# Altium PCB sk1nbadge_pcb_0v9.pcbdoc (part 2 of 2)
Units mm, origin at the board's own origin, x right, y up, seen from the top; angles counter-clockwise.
Board outline 99 x 74 mm, 4 copper layers (Top Layer, GND Plane, 3V Plane, Bottom Layer); 199 components, 158 nets, 800 pads, 392 vias.
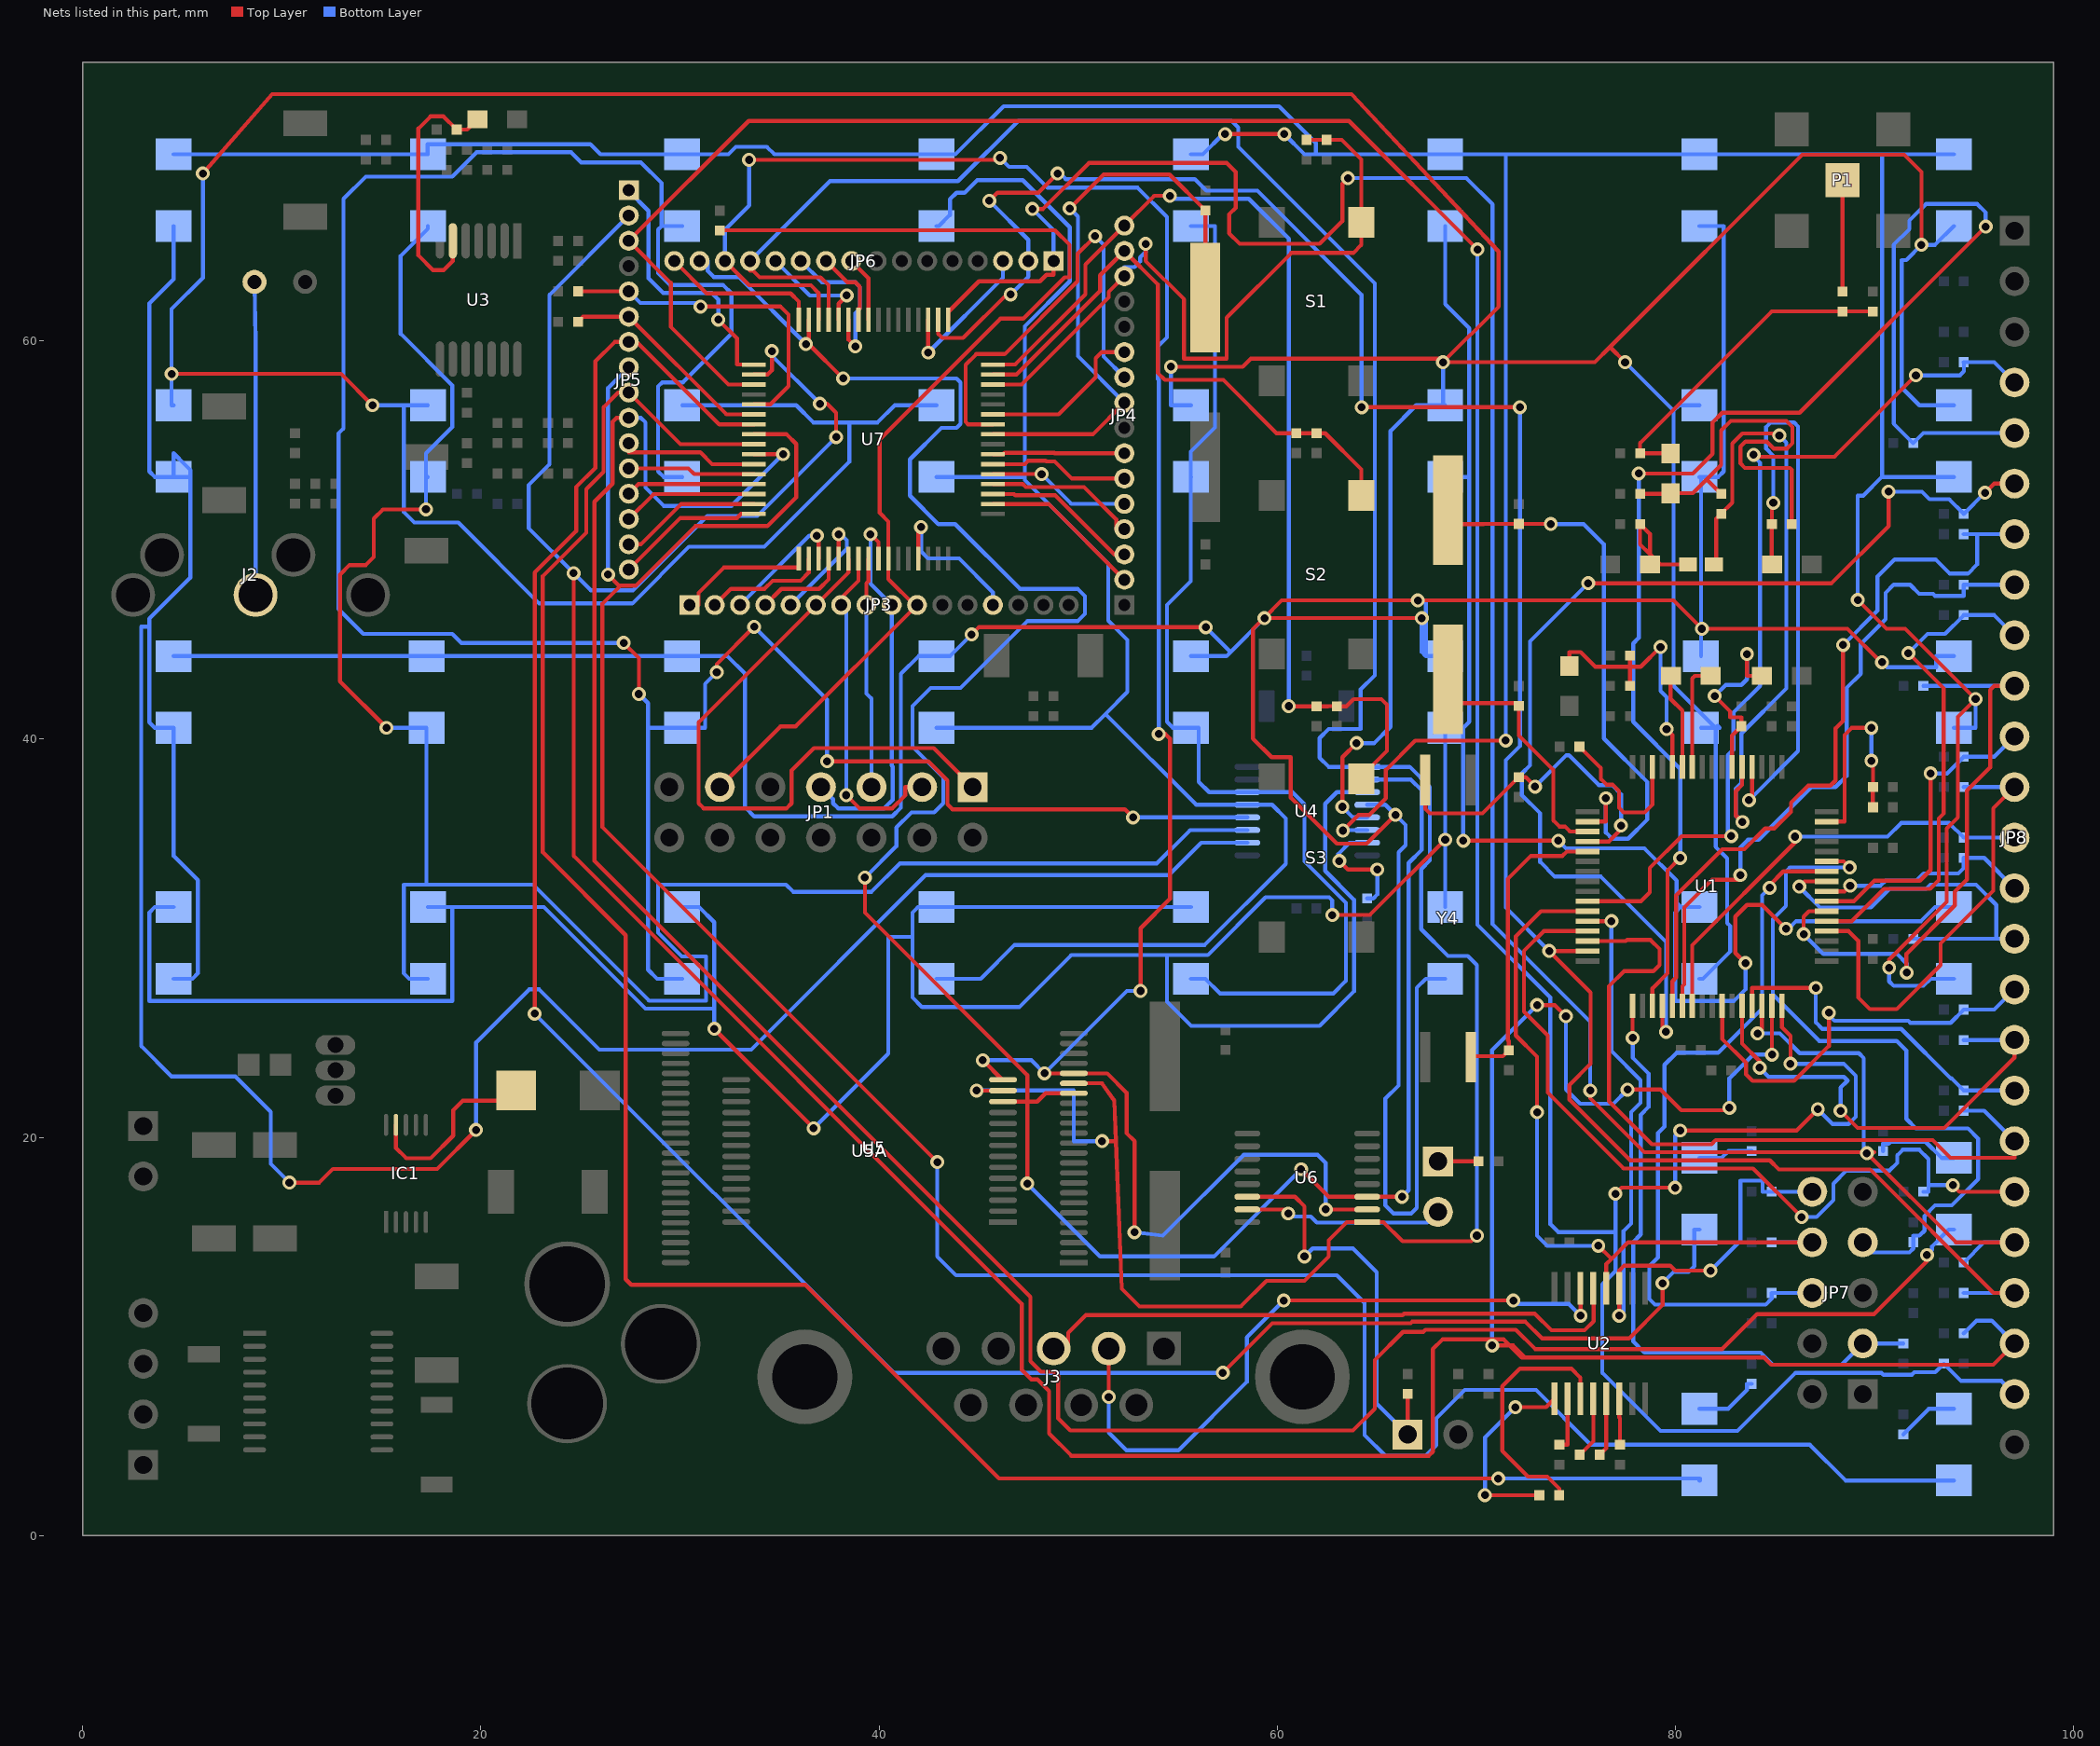
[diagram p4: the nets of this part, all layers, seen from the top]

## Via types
v1: diameter 0.7, hole 0.4, Top Layer to Bottom Layer, 392 vias

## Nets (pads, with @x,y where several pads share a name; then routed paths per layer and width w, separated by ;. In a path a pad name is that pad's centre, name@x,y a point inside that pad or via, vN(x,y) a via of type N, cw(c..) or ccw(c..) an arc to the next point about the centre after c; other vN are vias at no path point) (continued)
NetC27_2: C27.2 JP4.9 U7.9 Y2.1 | length 30.8
  Top Layer w0.2: U7.9@45.72,55.308 50.736,55.308 JP4.9@52.324,56.896 ; v1(49.581,66.65) 51.283,68.351 54.593,68.351 C27.2@56.388,66.556 Y2.1@56.388,62.162
  Bottom Layer w0.2: v1(49.581,66.65) 49.987,66.243 49.987,59.233 JP4.9@52.324,56.896
NetC29_2: C29.2 JP4.14 R27.1 S1.2@64.226,65.951 U7.14 | length 37.9
  Top Layer w0.2: U7.14@45.72,57.808 47.165,57.808 51.537,62.179 51.537,62.459 JP4.14@52.324,63.246 ; v1(53.391,64.872) 53.391,64.015 55.321,62.085 55.321,59.106 57.455,59.106 57.455,61.163 60.706,64.414 63.82,64.414 64.226,64.821 S1.2@64.226,65.951 64.226,69.113 63.243,70.096 C29.2@62.484,70.096 R27.1@61.468,70.096
  Bottom Layer w0.2: JP4.14@52.324,63.246 52.324,63.703 52.832,63.703 53.111,63.983 53.111,64.186 53.391,64.465 v1(53.391,64.872)
NetC30_2: C30.2 JP4.15 R28.1 S2.2@64.226,52.235 U7.15 | length 30
  Top Layer w0.2: U7.15@45.72,58.308 46.903,58.308 51.105,62.509 51.105,63.297 JP4.15@52.324,64.516 54,62.84 54,58.395 54.356,58.039 57.291,58.039 59.966,55.364 R28.1@60.96,55.364 C30.2@61.976,55.364 62.405,55.364 64.226,53.543 S2.2@64.226,52.235
NetC31_2: C31.2 JP4.16 R29.1 S3.2@64.226,38.011 U7.16 | length 53.1
  Top Layer w0.2: U7.16@45.72,58.808 46.838,58.808 50.368,62.339 50.368,63.83 JP4.16@52.324,65.786 53.823,67.285 v1(54.61,67.285) ; v1(60.579,41.656) 60.587,41.648 R29.1@61.976,41.648 62.552,41.648 62.56,41.656 62.984,41.656 C31.2@62.992,41.648 63.475,41.648 63.838,42.012 65.227,42.012 65.507,41.732 65.507,39.406 64.226,38.125 S3.2@64.226,38.011
  Bottom Layer w0.2: v1(54.61,67.285) 54.762,67.132 58.572,67.132 60.579,65.126 v1(60.579,41.656)
NetC32_1: C32.1 C37.2 C38.1 L2.1 | length 21.4
  Top Layer w0.2: C37.2@78.224,52.324 79.756,52.324 L2.1@79.756,52.34 79.756,52.349 80.874,52.349 81.568,53.044 ; C38.1@82.296,52.316 81.568,53.044 ; C32.1@85.844,50.8 85.844,53.526 85.75,53.619 83.49,53.619 83.261,53.848 83.261,54.686 83.515,54.94 84.582,54.94 84.938,54.585 85.598,54.585 85.877,54.864 85.877,55.677 85.573,55.982 82.779,55.982 82.296,55.499 82.296,53.772 81.568,53.044
NetC32_2: C32.2 L3.2 U1.4 | length 30.4
  Top Layer w0.2: v1(83.693,36.932) 83.844,37.083 U1.4@83.844,38.608 ; L3.2@84.852,48.768 84.836,48.768 84.836,50.513 84.844,50.521 C32.2@84.844,50.8 84.844,51.799 v1(84.912,51.867)
  Bottom Layer w0.2: v1(83.693,36.932) 86.157,39.395 86.157,55.702 85.954,55.905 84.785,55.905 84.557,55.677 84.557,54.585 84.912,54.229 v1(84.912,51.867)
NetC35_2: C35.2 R30.2 U1.63 | length 10.8
  Top Layer w0.2: U1.63@87.594,35.858 88.494,35.858 88.494,40.208 88.85,40.564 v1(89.84,40.564) ; v1(89.84,38.913) 89.924,38.829 R30.2@89.924,37.592 89.916,37.584 89.916,36.584 C35.2@89.924,36.576
  Bottom Layer w0.2: v1(89.84,38.913) v1(89.84,40.564)
NetC36_2: C36.2 L2.2 R62.1 R63.1 | length 16.5
  Top Layer w0.2: L2.2@79.756,54.34 79.756,54.356 C36.2@78.224,54.356 78.224,54.864 84.836,61.476 R63.1@89.916,61.476
NetC38_2: C38.2 L4.2 U1.5 | length 32.9
  Top Layer w0.2: L4.2@81.93,48.768 82.042,48.768 82.042,51.062 C38.2@82.296,51.316 82.855,51.875 82.855,54.846 83.356,55.347 84.861,55.347 84.963,55.245 v1(85.217,55.245) ; U1.5@83.344,38.608 83.344,37.7 83.033,37.389 83.033,36.17 v1(83.363,35.839)
  Bottom Layer w0.2: v1(83.363,35.839) 83.033,36.17 83.033,37.516 83.312,37.795 83.312,40.284 85.573,42.545 85.573,54.889 v1(85.217,55.245)
NetC39_2: C39.2 L4.1 L5.2 | length 5.9
  Top Layer w0.2: L5.2@78.724,48.768 L5.2@78.982,49.026 ; L4.1@80.63,48.768 79.24,48.768 L5.2@78.982,49.026 ; 78.724,49.284 78.724,50.3 C39.2@78.224,50.8 78.224,49.784 78.724,49.284 ; 78.724,49.284 L5.2@78.982,49.026
NetC44_2: C44.2 L6.2 U1.6 | length 9.7
  Top Layer w0.2: v1(81.966,42.164) 82.753,41.377 82.753,41.097 83.312,41.097 C44.2@83.312,40.648 82.844,40.18 U1.6@82.844,38.608 ; v1(83.591,44.272) 83.591,43.18 L6.2@84.344,43.18
  Bottom Layer w0.2: v1(81.966,42.164) 82.525,42.723 83.312,42.723 83.591,43.002 v1(83.591,44.272)
NetC45_2: C45.2 C46.2 L8.2 U1.12 | length 13.8
  Top Layer w0.2: L8.2@74.676,43.672 74.676,44.374 75.235,44.374 75.971,43.637 77.716,43.637 ; C45.2@77.716,42.672 77.716,43.637 ; C46.2@77.716,44.196 77.716,43.637 ; v1(79.248,44.628) 78.257,43.637 77.716,43.637 ; v1(79.553,40.499) 79.844,40.208 U1.12@79.844,38.608
  Bottom Layer w0.2: v1(79.248,44.628) 79.248,42.418 79.553,42.113 v1(79.553,40.499)
NetC48_1: C48.1 U1.18 Y3.1 | length 30.1
  Top Layer w0.2: Y3.1@68.58,51.494 68.58,50.8 70.35,50.8 70.358,50.808 C48.1@72.136,50.808 73.728,50.808 v1(73.736,50.8) ; U1.18@75.594,35.858 76.505,35.858 v1(76.505,37.033)
  Bottom Layer w0.2: v1(73.736,50.8) 75.387,50.8 76.403,49.784 76.403,40.03 78.588,37.846 78.588,35.966 77.622,35.001 76.81,35.001 76.505,35.306 v1(76.505,37.033)
NetC49_2: C49.2 U1.19 Y3.2 | length 13.2
  Top Layer w0.2: Y3.2@68.58,42.994 68.58,41.808 71.992,41.808 C49.2@72.136,41.664 72.136,40.183 73.863,38.456 73.863,35.916 74.168,35.611 74.449,35.611 74.701,35.358 U1.19@75.594,35.358
NetC50_2: C50.2 U1.20 Y4.1@67.435,37.945 | length 17.5
  Top Layer w0.2: Y4.1@67.435,37.945 67.435,36.502 67.666,36.271 70.307,36.271 72.128,38.092 C50.2@72.136,38.092 72.474,38.092 v1(72.949,37.617) ; U1.20@75.594,34.858 76.657,34.858 77.267,35.468 v1(77.267,35.662)
  Bottom Layer w0.2: v1(72.949,37.617) 74.524,39.192 74.651,39.192 76.149,37.694 76.81,37.694 77.267,37.236 v1(77.267,35.662)
NetC51_2: C51.2 U1.21 Y4.2@69.725,24.031 | length 15.3
  Top Layer w0.2: Y4.2@69.725,24.031 69.725,24.079 71.331,24.079 C51.2@71.628,24.376 71.628,24.841 71.577,24.892 71.577,32.969 72.746,34.138 74.32,34.138 74.541,34.358 U1.21@75.594,34.358
NetC53_1: C53.1 U2.3 | length 12.8
  Top Layer w0.2: C53.1@74.16,2.032 74.168,2.032 74.168,2.362 73.558,2.972 72.593,2.972 71.298,4.267 71.298,7.493 72.187,8.382 74.778,8.382 75.225,7.935 U2.3@75.225,6.877
NetC53_2: C53.2 U2.1 | length 9.9
  Top Layer w0.2: v1(70.434,2.032) C53.2@73.16,2.032 ; v1(71.958,6.452) 73.5,6.452 U2.1@73.925,6.877
  Bottom Layer w0.2: v1(70.434,2.032) 70.434,4.928 v1(71.958,6.452)
NetC54_2: C54.2 U2.2 | length 2.7
  Top Layer w0.2: C54.2@74.168,4.564 74.575,4.564 U2.2@74.575,6.877
NetC55_1: C55.1 U2.5 | length 3
  Top Layer w0.2: C55.1@76.192,4.064 76.525,4.397 U2.5@76.525,6.877
NetC55_2: C55.2 U2.4 | length 3.1
  Top Layer w0.2: C55.2@75.192,4.064 75.875,4.747 U2.4@75.875,6.877
NetC56_2: C56.2 U2.6 | length 2.3
  Top Layer w0.2: U2.6@77.175,6.877 77.175,5.944 77.216,5.903 C56.2@77.216,4.564
NetD1_1: D1.1 R17.2 U6.14 | length 20.7
  Top Layer w0.2: U6.14@58.496,17.018 60.884,17.018 61.366,16.535 v1(61.366,14.021) ; D1.1@66.548,5.08 R17.2@66.548,7.12
  Bottom Layer w0.2: v1(61.366,14.021) 61.773,14.427 63.805,14.427 64.999,13.233 64.999,6.629 D1.1@66.548,5.08
NetDS1_1: DS1.1 DS9.1 DS17.1 DS25.1 U4.10 | length 139.9
  Top Layer w0.2: v1(10.389,17.729) 11.887,17.729 12.573,18.415 17.805,18.415 v1(19.761,20.371)
  Bottom Layer w0.2: DS25.1@4.572,27.969 5.515,27.969 5.791,28.245 5.791,32.918 4.572,34.138 DS17.1@4.572,40.567 3.629,40.567 3.353,40.843 3.353,45.644 ; DS1.1@4.572,65.764 4.572,63.094 3.353,61.874 3.353,53.442 3.629,53.166 DS9.1@4.572,53.166 ; v1(10.389,17.729) 9.449,18.669 9.449,21.285 7.671,23.063 4.47,23.063 2.946,24.587 2.946,45.644 3.353,45.644 ; v1(19.761,20.371) 19.761,24.765 22.428,27.432 22.936,27.432 25.959,24.409 33.579,24.409 42.342,33.172 54.559,33.172 56.185,34.798 U4.10@58.496,34.798 ; 3.353,45.644 3.353,46.05 5.41,48.108 DS9.1@5.41,53.166 ; DS9.1@4.572,53.166 DS9.1@5.41,53.166 ; DS9.1@4.572,53.166 4.572,54.356 5.167,53.761 5.41,53.518 DS9.1@5.41,53.166
NetDS1_2: DS1.2 DS2.2 DS3.2 DS4.2 DS5.2 DS6.2 DS7.2 DS8.2 DS16.1 DS24.1 DS32.1 U4.6 | length 198.1
  Top Layer w0.2: v1(57.379,70.383) v1(60.35,70.383) ; v1(63.297,35.408) 64.084,36.195 64.618,36.195 65.456,37.033 65.456,38.456 66.929,39.929 v1(71.476,39.929) ; v1(89.154,46.99) 90.602,45.542 91.542,45.542 v1(95.072,42.012) 94.183,41.123 94.183,36.068 93.624,35.509 93.624,31.826 90.729,28.931 v1(90.729,28.524)
  Bottom Layer w0.2: DS1.2@4.572,69.364 DS2.2@17.323,69.364 ; DS2.2@17.345,69.364 DS2.2@17.323,69.364 ; DS5.2@55.662,69.364 56.261,69.364 57.28,70.383 v1(57.379,70.383) ; v1(60.35,70.383) 61.37,69.364 61.94,69.364 ; v1(63.297,35.408) 63.322,35.433 U4.6@64.516,35.433 ; v1(71.476,39.929) 71.476,69.367 ; v1(89.154,46.99) 89.154,52.222 89.43,52.222 90.373,53.166 ; v1(90.729,28.524) 90.729,27.838 90.957,27.61 92.453,27.61 92.812,27.969 DS32.1@93.98,27.969 ; DS24.1@93.98,40.567 95.072,40.567 v1(95.072,42.012) ; DS16.1@93.98,53.166 90.373,53.166 ; DS8.2@93.98,69.364 90.373,69.364 ; DS2.2@17.323,69.364 17.323,69.875 17.345,69.875 25.502,69.875 26.013,69.364 DS3.2@30.117,69.364 32.432,69.364 32.817,69.748 34.363,69.748 34.747,69.364 DS4.2@42.89,69.364 43.84,69.364 46.257,71.78 60.093,71.78 61.94,69.934 61.94,69.364 ; 61.94,69.364 DS6.2@68.435,69.364 68.438,69.367 71.476,69.367 ; 71.476,69.367 78,69.367 78.003,69.364 DS7.2@81.207,69.364 90.373,69.364 ; 90.373,53.166 90.373,69.364
NetDS2_1: DS2.1 DS10.1 DS18.1 DS26.1 U4.11 | length 103.8
  Top Layer w0.2: v1(15.265,40.567) 12.929,42.904 12.929,48.26 13.411,48.743 14.224,48.743 14.63,49.149 14.63,51.079 15.088,51.537 v1(17.247,51.537)
  Bottom Layer w0.2: v1(15.265,40.567) DS18.1@17.272,40.567 17.272,32.69 ; v1(17.247,51.537) DS10.1@17.247,53.166 ; DS26.1@17.345,27.969 16.405,27.969 16.129,28.245 16.129,32.69 17.272,32.69 ; DS10.1@17.345,53.166 DS10.1@17.247,53.166 ; DS2.1@17.345,65.764 17.345,65.63 15.977,64.262 15.977,60.35 18.567,57.76 18.567,55.677 17.247,54.356 DS10.1@17.247,53.166 ; U4.11@58.496,35.433 55.626,35.433 53.95,33.757 41.046,33.757 39.624,32.334 35.687,32.334 35.331,32.69 28.905,32.69 28.905,30.277 30.099,29.083 31.318,29.083 31.318,26.869 28.452,26.869 22.631,32.69 17.272,32.69
NetDS3_1: DS3.1 DS11.1 DS19.1 DS27.1 U4.12 | length 134.5
  Top Layer w0.2: v1(27.178,44.831) 27.94,44.069 v1(27.94,42.266) ; v1(31.852,43.358) 31.852,43.764 v1(33.731,45.644) ; v1(37.389,38.887) 42.469,38.887 43.434,37.922 43.434,36.728 43.688,36.474 52.349,36.474 v1(52.756,36.068)
  Bottom Layer w0.2: v1(27.178,44.831) 19.025,44.831 18.567,45.288 14.097,45.288 12.852,46.533 12.852,55.347 13.106,55.601 13.106,67.132 14.224,68.25 18.567,68.25 19.787,69.469 24.536,69.469 25.044,68.961 28.042,68.961 29.083,67.92 29.083,65.764 ; v1(27.94,42.266) 28.397,41.808 28.397,40.567 ; DS27.1@30.117,27.969 28.851,27.969 28.397,28.423 28.397,40.567 ; DS11.1@30.117,53.166 29.181,53.166 28.905,53.442 28.905,57.709 29.108,57.912 30.15,57.912 32.588,60.35 32.588,62.382 32.163,62.808 29.496,62.808 28.905,63.398 28.905,65.586 29.083,65.764 ; DS3.1@30.117,65.764 29.083,65.764 ; v1(31.852,43.358) 31.267,42.774 31.267,40.567 DS19.1@30.117,40.567 28.397,40.567 ; v1(33.731,45.644) 37.389,41.986 v1(37.389,38.887) ; v1(52.756,36.068) U4.12@58.496,36.068
NetDS4_1: DS4.1 DS12.1 DS20.1 DS28.1 U4.13 | length 83.7
  Bottom Layer w0.2: DS28.1@42.89,27.969 45.114,27.969 46.812,29.667 56.363,29.667 60.427,33.731 60.427,36.017 59.741,36.703 U4.13@58.496,36.703 55.931,36.703 51.371,41.262 ; DS20.1@42.89,40.567 50.676,40.567 51.371,41.262 ; DS12.1@42.89,53.166 47.32,53.166 ; DS4.1@42.89,65.764 43.006,65.764 43.561,66.319 43.561,67.107 43.891,67.437 44.298,67.437 44.933,68.072 47.219,68.072 49.581,65.71 49.581,62.992 47.32,60.731 47.32,53.166 ; 47.32,53.166 47.32,53.013 51.511,48.822 51.511,45.949 52.476,44.983 52.476,42.367 51.371,41.262
NetDS5_1: DS5.1 DS13.1 DS21.1 DS29.1 U4.14 | length 55.4
  Bottom Layer w0.2: DS29.1@55.662,27.969 56.388,27.969 57.128,27.229 62.814,27.229 63.449,27.864 63.449,31.775 61.366,33.858 61.366,36.728 60.757,37.338 U4.14@58.496,37.338 56.577,37.338 56.058,37.857 56.058,40.567 DS21.1@55.662,40.567 54.759,40.567 54.458,40.869 54.458,46.736 55.651,47.93 DS13.1@55.651,53.166 ; DS13.1@55.662,53.166 DS13.1@55.651,53.166 ; DS5.1@55.662,65.764 56.871,65.764 56.871,55.651 55.651,54.432 DS13.1@55.651,53.166
NetDS6_1: DS6.1 DS14.1 DS22.1 DS25.2 DS26.2 DS27.2 DS28.2 DS29.2 DS30.2 DS31.2 DS32.2 U4.3 | length 225.4
  Top Layer w0.2: v1(31.725,25.451) v1(36.716,20.46) ; v1(62.763,31.166) 64.65,31.166 v1(68.435,34.95) ; v1(69.342,34.9) v1(74.117,34.9) ; v1(83.515,28.753) 83.007,29.261 83.007,31.09 83.591,31.674 84.353,31.674 v1(85.547,30.48)
  Bottom Layer w0.2: DS25.2@4.572,31.569 3.629,31.569 3.353,31.293 3.353,26.848 18.567,26.848 18.567,31.569 ; DS26.2@17.345,31.569 18.567,31.569 ; DS27.2@30.117,31.569 30.966,31.569 31.725,30.81 31.725,26.467 ; v1(31.725,25.451) 31.725,26.467 ; v1(36.716,20.46) 40.462,24.206 40.462,30.074 41.681,30.074 ; DS29.2@55.662,31.569 DS28.2@42.89,31.569 41.957,31.569 41.681,31.293 41.681,30.074 ; v1(62.763,31.166) 62.763,31.895 62.604,32.055 59.411,32.055 56.515,29.159 54.458,29.159 ; U4.3@64.516,37.338 62.992,37.338 62.408,36.754 62.408,33.383 63.856,31.935 63.856,27.33 62.128,25.603 55.677,25.603 54.458,26.822 54.458,29.159 ; DS30.2@68.435,31.569 v1(68.435,34.95) DS22.1@68.435,40.567 69.342,40.567 ; DS14.1@68.435,53.166 69.647,53.166 ; DS6.1@68.435,65.764 68.435,61.842 69.647,60.63 69.647,53.166 ; v1(69.342,34.9) 69.342,40.567 ; v1(74.117,34.9) 74.498,34.519 78.435,34.519 80.061,32.893 80.061,31.772 80.264,31.569 ; DS31.2@81.207,31.569 80.264,31.569 ; v1(83.515,28.753) 83.515,27.432 82.931,26.848 79.985,26.848 79.985,31.293 80.261,31.569 80.264,31.569 ; v1(85.547,30.48) 85.674,30.48 86.055,30.861 92.332,30.861 93.04,31.569 DS32.2@93.98,31.569 ; 18.567,31.569 23.165,31.569 28.267,26.467 31.725,26.467 ; 41.681,30.074 41.681,27.026 42.164,26.543 47.041,26.543 49.657,29.159 54.458,29.159 ; 69.342,40.567 69.647,40.872 69.647,53.166
NetDS7_1: DS7.1 DS15.1 DS17.2 DS18.2 DS19.2 DS20.2 DS21.2 DS22.2 DS23.2 DS24.2 DS30.1 U4.4 | length 202
  Top Layer w0.2: v1(44.653,45.259) 45.012,45.618 v1(56.413,45.618) ; v1(59.36,46.076) v1(67.259,46.076) ; v1(65.938,36.195) 64.491,34.747 62.992,34.747 60.681,37.059 60.681,39.091 59.715,39.091 58.776,40.03 58.776,45.517 59.347,46.088 60.223,46.965 v1(67.056,46.965) 79.908,46.965 v1(81.331,45.542) 88.639,45.542 90.315,43.866 v1(90.373,43.866)
  Bottom Layer w0.2: DS17.2@4.572,44.167 DS18.2@17.272,44.167 DS19.2@30.117,44.167 32.388,44.167 33.274,43.282 33.274,36.576 33.731,36.119 40.665,36.119 41.097,36.551 41.097,43.282 41.983,44.167 DS20.2@42.89,44.167 43.561,44.167 v1(44.653,45.259) ; DS21.2@55.662,44.167 57.451,44.167 57.658,44.374 ; v1(56.413,45.618) 57.658,44.374 ; v1(59.36,46.076) 57.658,44.374 ; U4.4@64.516,36.703 65.43,36.703 v1(65.938,36.195) 66.446,35.687 66.446,34.671 66.091,34.315 66.091,22.606 65.43,21.946 65.43,16.586 65.837,16.18 66.726,16.18 67.005,16.459 67.005,27.512 67.462,27.969 DS30.1@68.435,27.969 ; v1(67.056,46.965) 67.462,46.965 67.462,46.076 67.462,44.167 ; v1(67.259,46.076) 67.259,44.37 67.462,44.167 ; DS22.2@68.435,44.167 67.462,44.167 ; DS15.1@81.207,53.166 DS15.1@81.28,53.166 ; DS7.1@81.207,65.764 82.423,65.764 82.423,53.442 82.147,53.166 DS15.1@81.28,53.166 ; DS23.2@81.28,44.167 v1@81.28,45.542 ; v1(81.331,45.542) v1@81.28,45.542 ; v1(90.373,43.866) 90.627,43.612 93.091,43.612 93.091,44.167 DS24.2@93.98,44.167 ; v1@81.28,45.542 DS15.1@81.28,53.166
NetDS8_1: DS8.1 DS9.2 DS10.2 DS11.2 DS12.2 DS13.2 DS14.2 DS15.2 DS16.2 DS23.1 DS31.1 U4.5 | length 277.8
  Top Layer w0.2: v1(4.47,58.344) 12.979,58.344 v1(14.558,56.766) ; v1(6.045,68.402) 9.525,72.39 63.729,72.39 71.12,64.491 71.12,61.722 v1(68.326,58.928) ; v1(54.661,58.699) 58.268,58.699 58.674,59.106 68.148,59.106 v1(68.326,58.928) ; v1(63.271,36.601) 63.271,39.091 v1(63.983,39.802) ; v1(77.47,58.928) 76.708,59.69 ; v1(92.354,64.821) 92.354,68.478 91.491,69.342 86.36,69.342 76.708,59.69 ; v1(68.326,58.928) 75.946,58.928 76.708,59.69
  Bottom Layer w0.2: DS9.2@4.572,56.766 4.47,56.766 v1(4.47,58.344) 4.47,61.595 6.045,63.17 v1(6.045,68.402) ; v1(14.558,56.766) 16.129,56.766 ; DS10.2@17.345,56.766 16.129,56.766 ; DS11.2@30.117,56.766 35.839,56.766 36.7,55.905 38.506,55.905 ; DS12.2@42.89,56.766 40.789,56.766 39.929,55.905 38.506,55.905 ; v1(54.661,58.699) 54.661,56.766 DS13.2@55.662,56.766 ; v1(63.271,36.601) 63.805,36.068 U4.5@64.516,36.068 ; v1(63.983,39.802) 64.872,39.802 65.684,40.615 65.684,55.474 66.976,56.766 DS14.2@68.326,56.766 ; v1(68.326,58.928) DS14.2@68.326,56.766 ; DS14.2@68.435,56.766 DS14.2@68.326,56.766 ; v1(77.47,58.928) 79.908,56.49 ; DS31.1@81.207,27.969 81.382,27.969 82.753,29.34 82.753,30.607 82.601,30.759 82.601,34.011 82.017,34.595 DS23.1@82.017,40.567 ; DS15.2@81.207,56.766 80.184,56.766 79.908,56.49 ; DS23.1@81.28,40.567 DS23.1@82.017,40.567 ; DS16.2@93.98,56.766 92.253,56.766 91.364,57.655 91.364,64.059 91.592,64.059 v1(92.354,64.821) 93.037,64.821 DS8.1@93.98,65.764 ; 16.129,56.766 16.129,51.41 16.662,50.876 18.872,50.876 22.936,46.812 27.61,46.812 30.455,49.657 34.239,49.657 38.506,53.924 38.506,55.905 ; 79.908,56.49 79.908,42.675 81.648,40.936 DS23.1@82.017,40.567 ; DS23.1@82.017,40.567 82.118,40.669 82.22,40.567 DS23.1@82.017,40.567
NetDS33_1: DS33.1 R16.1 | length 2
  Top Layer w0.2: DS33.1@68.072,18.796 R16.1@70.112,18.796
NetDS33_2: DS33.2 U6.15 | length 10.1
  Top Layer w0.2: U6.15@58.496,16.383 60.35,16.383 v1(60.554,16.18)
  Bottom Layer w0.2: v1(60.554,16.18) 60.706,16.027 61.682,16.027 61.986,15.723 67.539,15.723 DS33.2@68.072,16.256
NetDS34_1: DS34.1 JP5.10 U7.42 | length 127.3
  Top Layer w0.2: JP5.10@27.432,56.134 26.822,56.134 26.619,55.931 26.619,52.832 25.705,51.918 25.705,33.884 47.6,11.989 47.6,8.761 48.131,8.23 48.789,8.23 48.997,8.022 48.997,5.893 49.606,5.283 63.805,5.283 64.897,6.375 64.897,8.814 66.319,10.236 67.335,10.236 67.437,10.338 71.984,10.338 72.949,9.373 82.347,9.373 84.099,11.125 89.967,11.125 92.634,13.792 v1(92.634,14.097) ; U7.42@33.72,54.308 v1(35.179,54.308)
  Bottom Layer w0.2: JP5.10@27.432,56.134 28.042,56.134 28.27,55.905 28.27,52.629 29.185,51.714 32.585,51.714 v1(35.179,54.308) ; v1(92.634,14.097) 92.888,14.351 92.888,14.532 93.726,15.37 DS34.1@93.98,15.37
NetDS34_2: DS34.2 R20.1 | length 4.3
  Bottom Layer w0.2: R20.1@90.424,19.312 90.424,19.685 90.703,19.685 90.805,19.787 92.554,19.787 93.37,18.97 DS34.2@93.98,18.97
NetDS35_1: DS35.1 JP5.8 U7.40 | length 131.5
  Top Layer w0.2: v1(26.391,48.26) 26.949,47.701 27.003,47.701 ; U7.40@33.72,55.308 35.357,55.308 35.839,54.825 35.839,52.146 34.392,50.698 30.772,50.698 27.775,47.701 27.003,47.701 ; v1(42.926,18.764) 26.111,35.578 26.111,46.809 27.003,47.701
  Bottom Layer w0.2: v1(26.391,48.26) 26.391,57.633 JP5.8@27.432,58.674 ; v1(42.926,18.764) 42.926,14.021 43.866,13.081 62.992,13.081 64.389,11.684 64.389,5.055 65.43,4.013 67.462,4.013 67.996,4.547 67.996,5.893 69.418,7.315 73,7.315 75.743,4.572 86.744,4.572 88.544,2.772 DS35.1@93.98,2.772
NetDS35_2: DS35.2 R22.1 | length 3.1
  Bottom Layer w0.2: R22.1@91.44,5.088 92.724,6.372 DS35.2@93.98,6.372
NetDS36_1: DS36.1 JP5.9 U7.41 | length 113.9
  Top Layer w0.2: U7.41@33.72,54.808 30.028,54.808 JP5.9@27.432,57.404 26.899,57.404 26.162,56.667 26.162,53.416 25.298,52.553 25.298,50.368 23.114,48.184 23.114,34.315 27.28,30.15 27.28,12.878 27.559,12.598 36.297,12.598 46.025,2.87 v1(71.095,2.87)
  Bottom Layer w0.2: v1(71.095,2.87) 81.207,2.87 81.229,2.87 81.229,2.772 DS36.1@81.207,2.772
NetDS36_2: DS36.2 R21.1 | length 3.3
  Bottom Layer w0.2: DS36.2@81.207,6.372 82.648,6.372 83.591,7.315 83.591,7.628 R21.1@83.82,7.628
NetDS37_1: DS37.1 JP5.7 U7.39 | length 115.5
  Top Layer w0.2: v1(22.708,26.213) 22.708,48.362 24.79,50.444 24.79,52.654 25.756,53.619 25.756,58.979 26.721,59.944 JP5.7@27.432,59.944 27.838,59.944 31.974,55.808 U7.39@33.72,55.808 ; v1(57.264,8.179) 59.753,10.668 66.7,10.668 66.777,10.744 72.466,10.744 73.304,9.906 77.673,9.906 79.35,11.582 v1(79.35,12.675)
  Bottom Layer w0.2: v1(22.708,26.213) 40.742,8.179 v1(57.264,8.179) ; v1(79.35,12.675) 79.934,13.259 80.67,13.259 80.95,13.538 80.95,15.37 DS37.1@81.207,15.37
NetDS37_2: DS37.2 R23.1 | length 2.8
  Bottom Layer w0.2: DS37.2@81.207,18.97 82.321,18.97 82.663,19.312 R23.1@83.82,19.312
NetIC1_9: IC1.9 L1.1 | length 9.6
  Top Layer w0.2: IC1.9@15.74,20.628 15.74,19.464 16.256,18.948 17.475,18.948 18.618,20.091 18.618,21.361 19.101,21.844 21.268,21.844 L1.1@21.776,22.352
NetJ2_2: J2.2 MK1.2 | length 15.7
  Bottom Layer w0.2: MK1.2@8.636,62.96 8.69,59.998 J2.2@8.69,47.244
NetJ3_2: J3.2 U2.14 | length 34.4
  Top Layer w0.2: v1(51.537,6.96) 51.538,6.961 J3.2@51.538,9.396 ; v1(60.325,11.811) v1(71.857,11.811) ; U2.14@75.225,12.427 75.225,11.887 75.235,11.877 v1(75.235,11.049)
  Bottom Layer w0.2: v1(51.537,6.96) 51.537,5.182 52.426,4.293 55.042,4.293 58.471,7.722 58.471,9.957 v1(60.325,11.811) ; v1(71.857,11.811) 72.034,11.633 74.651,11.633 v1(75.235,11.049)
NetJ3_3: J3.3 U2.13 | length 30.5
  Top Layer w0.2: J3.3@48.768,9.396 49.505,9.396 49.505,10.185 50.394,11.074 66.292,11.074 66.368,11.151 72.93,11.151 73.768,10.312 75.438,10.312 75.895,10.77 75.895,11.689 75.875,11.709 U2.13@75.875,12.427
NetJP1_1: JP1.1 JP3.6 U7.54 | length 32.3
  Top Layer w0.2: U7.54@38.47,49.058 38.47,48.376 JP3.6@36.83,46.736 30.937,40.843 30.937,36.779 31.191,36.525 35.357,36.525 35.611,36.779 35.611,38.424 36.734,39.548 42.748,39.548 JP1.1@44.704,37.592
NetJP1_3: JP1.3 JP3.7 U7.55 | length 17.1
  Top Layer w0.2: JP3.7@38.1,46.736 38.1,47.085 38.97,47.955 U7.55@38.97,49.058 ; v1(38.354,37.186) 39.014,36.525 40.665,36.525 41.326,37.186 41.326,37.592 JP1.3@42.164,37.592
  Bottom Layer w0.2: JP3.7@38.1,46.736 38.354,46.482 v1(38.354,37.186)
NetJP1_5: JP1.5 JP3.8 U7.56 | length 11.6
  Top Layer w0.2: JP3.8@39.37,46.736 39.37,47.828 39.47,47.928 U7.56@39.47,49.058
  Bottom Layer w0.2: JP3.8@39.37,46.736 39.37,42.291 39.624,42.037 JP1.5@39.624,37.592
NetJP1_7: JP1.7 JP3.9 U7.57 | length 19.5
  Top Layer w0.2: v1(39.573,50.292) 39.97,49.895 U7.57@39.97,49.058
  Bottom Layer w0.2: JP1.7@37.084,37.592 37.694,36.982 37.694,36.779 37.948,36.525 40.259,36.525 40.691,36.957 40.691,38.617 40.64,38.667 JP3.9@40.64,46.736 39.573,47.803 v1(39.573,50.292)
NetJP1_11: JP1.11 JP3.10 R19.1 U7.58 | length 55.2
  Top Layer w0.2: JP1.11@32.004,37.592 35.052,40.64 35.814,40.64 JP3.10@41.841,46.667 ; R19.1@32.004,65.54 32.004,65.557 48.831,65.557 49.568,64.821 49.568,63.195 49.327,63.195 47.244,61.112 46.094,61.112 40.03,55.049 40.03,51.367 40.47,50.927 U7.58@40.47,49.058 40.47,48.037 JP3.10@41.841,46.667 ; JP3.10@41.91,46.736 JP3.10@41.841,46.667
NetJP3_1: JP3.1 U7.49 | length 7.1
  Top Layer w0.2: JP3.1@30.48,46.736 30.937,46.736 30.937,47.346 32.207,48.616 35.97,48.616 U7.49@35.97,49.058
NetJP3_2: JP3.2 U7.50 | length 6.1
  Top Layer w0.2: JP3.2@31.75,46.736 32.563,47.549 34.252,47.549 34.658,47.955 36.064,47.955 36.47,48.362 U7.50@36.47,49.058
NetJP3_3: JP3.3 U7.51 | length 6.5
  Top Layer w0.2: v1(36.881,50.216) 36.97,50.127 U7.51@36.97,49.058
  Bottom Layer w0.2: JP3.3@33.02,46.736 36.5,50.216 v1(36.881,50.216)
NetJP3_4: JP3.4 U7.52 | length 4.7
  Top Layer w0.2: JP3.4@34.29,46.736 35.097,47.543 36.989,47.543 37.47,48.024 U7.52@37.47,49.058
NetJP3_5: JP3.5 U7.53 | length 6.2
  Top Layer w0.2: U7.53@37.97,49.058 37.97,50.289 v1(37.973,50.292)
  Bottom Layer w0.2: JP3.5@35.56,46.736 38.379,49.555 38.379,49.987 38.075,50.292 v1(37.973,50.292)
NetJP3_13: JP3.13 U7.61 | length 8
  Top Layer w0.2: U7.61@41.97,49.058 41.97,50.504 v1(42.113,50.648)
  Bottom Layer w0.2: v1(42.113,50.648) 42.113,49.421 42.462,49.073 44.018,49.073 45.72,47.371 JP3.13@45.72,46.736
NetJP4_2: JP4.2 U7.2 | length 8.2
  Top Layer w0.2: U7.2@45.72,51.808 48.522,51.808 JP4.2@52.324,48.006
NetJP4_3: JP4.3 U7.3 | length 7.9
  Top Layer w0.2: U7.3@45.72,52.308 46.787,52.308 46.847,52.248 48.844,52.248 51.816,49.276 JP4.3@52.324,49.276
NetJP4_4: JP4.4 U7.4 | length 7.8
  Top Layer w0.2: U7.4@45.72,52.808 47.219,52.808 47.372,52.654 50.292,52.654 51.918,51.029 51.918,50.546 JP4.4@52.324,50.546
NetJP4_5: JP4.5 U7.5 | length 7.2
  Top Layer w0.2: U7.5@45.72,53.308 v1(48.165,53.308)
  Bottom Layer w0.2: v1(48.165,53.308) 49.657,51.816 JP4.5@52.324,51.816
NetJP4_6: JP4.6 U7.6 | length 7
  Top Layer w0.2: U7.6@45.72,53.808 47.32,53.808 47.487,53.975 48.37,53.975 48.395,53.95 48.819,53.95 49.682,53.086 JP4.6@52.324,53.086
NetJP4_7: JP4.7 U7.7 | length 6.6
  Top Layer w0.2: U7.7@45.72,54.308 46.228,54.308 46.301,54.381 48.793,54.381 48.819,54.356 JP4.7@52.324,54.356
NetJP4_10: JP4.10 U7.10 | length 22
  Top Layer w0.2: U7.10@45.72,55.808 44.471,55.808 44.348,55.931 44.348,58.801 44.882,59.334 46.31,59.334 49.968,62.992 49.968,64.37 v1(50.851,65.253)
  Bottom Layer w0.2: v1(50.851,65.253) 51.283,64.821 51.283,59.207 JP4.10@52.324,58.166
NetJP4_11: JP4.11 U7.11 | length 8.5
  Top Layer w0.2: U7.11@45.72,56.308 49.018,56.308 50.876,58.166 50.876,59.131 51.181,59.436 JP4.11@52.324,59.436
NetJP5_1: JP5.1 U7.33 | length 13.3
  Top Layer w0.2: v1(31.928,61.062) 32.868,60.122 32.868,58.808 U7.33@33.72,58.808
  Bottom Layer w0.2: JP5.1@27.432,67.564 27.432,67.513 28.423,66.523 28.423,63.144 29.159,62.408 31.598,62.408 31.928,62.078 v1(31.928,61.062)
NetJP5_5: JP5.5 R26.1 U7.37 | length 16.8
  Top Layer w0.2: R26.1@24.884,62.484 JP5.5@27.432,62.484 ; v1(31.039,61.722) 35.052,61.722 35.458,61.316 35.458,57.722 34.544,56.808 U7.37@33.72,56.808
  Bottom Layer w0.2: JP5.5@27.432,62.484 28.016,61.9 30.861,61.9 v1(31.039,61.722)
NetJP5_6: JP5.6 R24.1 U7.38 | length 11
  Top Layer w0.2: R24.1@24.884,60.96 25.138,61.214 JP5.6@27.432,61.214 32.338,56.308 U7.38@33.72,56.308
NetJP5_11: JP5.11 U7.43 | length 7
  Top Layer w0.2: JP5.11@27.432,54.864 27.432,54.407 31.024,54.407 31.623,53.808 U7.43@33.72,53.808
NetJP5_12: JP5.12 U7.44 | length 6.4
  Top Layer w0.2: JP5.12@27.432,53.594 30.429,53.594 30.715,53.308 U7.44@33.72,53.308
NetJP5_13: JP5.13 U7.45 | length 6.5
  Top Layer w0.2: JP5.13@27.432,52.324 27.916,52.808 U7.45@33.72,52.808
NetJP5_14: JP5.14 U7.46 | length 6.8
  Top Layer w0.2: JP5.14@27.432,51.054 28.686,52.308 U7.46@33.72,52.308
NetJP5_15: JP5.15 U7.47 | length 7.1
  Top Layer w0.2: JP5.15@27.432,49.784 28.042,49.784 30.066,51.808 U7.47@33.72,51.808
NetJP5_16: JP5.16 U7.48 | length 7.4
  Top Layer w0.2: JP5.16@27.432,48.514 30.023,51.105 32.868,51.105 33.071,51.308 U7.48@33.72,51.308
NetJP6_3: JP6.3 U7.19 | length 7.8
  Top Layer w0.2: v1(42.469,59.411) v1(42.469,59.411) U7.19@42.47,61.058
  Bottom Layer w0.2: v1(42.469,59.411) 46.228,63.17 JP6.3@46.228,64.008
NetJP6_9: JP6.9 U7.25 | length 3.3
  Top Layer w0.2: JP6.9@38.608,64.008 39.47,63.146 U7.25@39.47,61.058
NetJP6_10: JP6.10 U7.26 | length 4
  Top Layer w0.2: JP6.10@37.338,64.008 38.405,62.941 38.811,62.941 39.04,62.713 39.04,61.62 38.97,61.62 U7.26@38.97,61.058
NetJP6_11: JP6.11 U7.27 | length 8.1
  Top Layer w0.2: U7.27@38.47,61.058 38.47,60.057 v1(38.811,59.715)
  Bottom Layer w0.2: JP6.11@36.068,64.008 37.135,62.941 38.811,62.941 39.04,62.713 39.04,61.62 38.811,61.392 v1(38.811,59.715)
NetJP6_12: JP6.12 U7.28 | length 5.7
  Top Layer w0.2: U7.28@37.97,61.058 37.97,61.871 v1(38.379,62.281)
  Bottom Layer w0.2: JP6.12@34.798,64.008 36.525,62.281 v1(38.379,62.281)
NetJP6_16: JP6.16 U7.32 | length 8
  Top Layer w0.2: JP6.16@29.718,64.008 31.344,62.382 35.564,62.382 35.97,61.976 U7.32@35.97,61.058
NetL7_1: L7.1 U1.11 | length 4.8
  Top Layer w0.2: L7.1@79.772,43.18 79.756,43.18 79.756,42.021 80.344,41.433 U1.11@80.344,38.608
NetL7_2: L7.2 U1.10 | length 5.4
  Top Layer w0.2: U1.10@80.844,38.608 80.844,43.049 80.975,43.18 L7.2@81.772,43.18
NetP1_1: P1.1 R62.2 | length 5.6
  Top Layer w0.2: R62.2@88.392,62.476 P1.1@88.392,68.072
NetR9_2: R9.2 R10.1 U3.6 | length 13.3
  Top Layer w0.2: U3.6@18.594,65.024 18.594,64.008 18.137,63.551 17.602,63.551 16.866,64.287 16.866,70.663 17.475,71.272 18.128,71.272 R10.1@18.788,70.612 19.32,70.612 R9.2@19.828,71.12
NetR18_2: R18.2 U4.7 | length 6
  Top Layer w0.2: v1(63.119,33.884) 63.551,33.452 v1(65.024,33.452)
  Bottom Layer w0.2: v1(63.119,33.884) 63.068,33.934 63.068,34.239 63.627,34.798 U4.7@64.516,34.798 ; R18.2@64.516,31.996 64.821,31.996 65.024,32.199 v1(65.024,33.452)
NetR31_2: R31.2 U1.14 | length 7.9
  Top Layer w0.2: R31.2@75.176,39.624 76.251,38.549 76.251,37.998 76.53,37.719 76.835,37.719 77.165,37.389 77.165,36.551 77.394,36.322 78.446,36.322 78.844,36.72 U1.14@78.844,38.608
P0_3: JP8.12 R51.1 U1.52 | length 23
  Top Layer w0.2: U1.52@87.594,30.358 88.692,30.358 89.179,29.87 89.179,27.026 89.764,26.441 91.11,26.441 93.32,28.651 93.32,29.743 95.961,32.385 95.961,36.525 JP8.12@97.028,37.592
  Bottom Layer w0.2: R51.1@94.48,37.592 JP8.12@97.028,37.592
P1_0: JP8.4 R59.1 U1.26 | length 45.1
  Top Layer w0.2: U1.26@75.594,31.858 78.264,31.858 78.715,32.309 78.715,33.528 80.315,35.128 v1(82.804,35.128) ; v1(83.922,54.28) 84.023,54.178 87.986,54.178 v1(92.075,58.268)
  Bottom Layer w0.2: v1(82.804,35.128) 82.626,35.306 82.626,39.192 82.906,39.472 82.906,41.326 84.252,42.672 84.252,53.873 83.922,54.204 v1(83.922,54.28) ; v1(92.075,58.268) 94.285,58.268 94.488,58.471 R59.1@94.488,58.928 ; R59.1@94.48,58.928 R59.1@94.488,58.928 ; JP8.4@97.028,57.912 96.012,58.928 R59.1@94.488,58.928
P1_1: JP8.5 R58.1 U1.35 | length 74.2
  Top Layer w0.2: v1(78.156,53.34) 80.874,53.34 81.864,54.331 81.864,55.905 82.347,56.388 86.233,56.388 v1(95.58,65.735) ; U1.35@78.844,26.608 78.844,27.485 79.604,28.245 79.604,33.401 v1(80.239,34.036)
  Bottom Layer w0.2: v1(78.156,53.34) 78.156,45.085 77.876,44.806 77.876,40.869 80.239,38.506 v1(80.239,34.036) ; v1(95.58,65.735) 95.58,66.446 95.148,66.878 92.583,66.878 91.745,66.04 91.745,65.608 90.957,64.821 90.957,55.847 R58.1@91.94,54.864 92.448,55.372 JP8.5@97.028,55.372
P1_2: JP8.6 R57.1 U1.36 | length 55.1
  Top Layer w0.2: v1(75.616,47.828) 87.833,47.828 90.703,50.698 v1(90.703,52.426) ; U1.36@79.344,26.608 79.344,25.482 v1(79.527,25.298) ; v1(95.547,52.375) 96.004,52.832 JP8.6@97.028,52.832
  Bottom Layer w0.2: v1(75.616,47.828) 72.695,44.907 72.695,38.684 72.288,38.278 72.288,37.186 73.203,36.271 73.203,33.833 73.939,33.096 76.251,33.096 79.527,29.82 v1(79.527,25.298) ; v1(90.703,52.426) 92.38,52.426 92.761,52.045 93.743,52.045 R57.1@94.48,51.308 v1(95.547,52.375)
P1_3: JP8.7 R56.1 U1.37 | length 37.3
  Top Layer w0.2: U1.37@79.844,26.608 79.844,27.838 80.035,28.03 80.035,32.156 82.347,34.468 83.464,34.468 84.506,35.509 84.963,35.509 85.801,36.347 85.801,36.805 86.665,37.668 87.782,37.668 88.036,37.922 88.036,40.538 88.417,40.919 v1(88.417,44.729)
  Bottom Layer w0.2: v1(88.417,44.729) 90.145,46.457 90.145,48.158 91.008,49.022 93.066,49.022 93.777,48.311 94.691,48.311 95.148,48.768 95.148,50.292 ; R56.1@94.48,50.292 95.148,50.292 ; JP8.7@97.028,50.292 95.148,50.292
P1_4: JP8.8 R55.1 U1.38 | length 34.3
  Top Layer w0.2: U1.38@80.344,26.608 80.344,27.584 80.442,27.682 80.442,31.547 81.839,32.944 83.261,32.944 v1(83.261,33.172)
  Bottom Layer w0.2: v1(83.261,33.172) 83.261,34.569 83.642,34.95 84.176,34.95 86.817,37.592 88.036,37.592 88.595,38.151 88.595,42.57 89.306,43.282 89.306,44.78 90.551,46.025 90.551,47.346 90.957,47.752 91.781,47.752 92.238,47.295 92.939,47.295 93.04,47.193 94.48,47.193 R55.1@94.48,47.752 JP8.8@97.028,47.752
P1_5: JP8.9 R54.1 U1.53 | length 25.3
  Top Layer w0.2: U1.53@87.594,30.858 88.846,30.858 90.475,32.487 92.786,32.487 93.218,32.918 93.218,36.017 93.472,36.271 93.472,42.545 v1(91.694,44.323)
  Bottom Layer w0.2: v1(91.694,44.323) 92.659,45.288 93.54,45.288 R54.1@94.48,46.228 96.012,46.228 JP8.9@97.028,45.212
P1_6: JP8.10 R53.1 U1.54 | length 30.2
  Top Layer w0.2: v1(86.436,30.201) 86.436,31.09 86.705,31.358 U1.54@87.594,31.358 ; v1(91.618,28.27) 91.592,28.296 91.592,29.21 94.031,31.648 94.031,32.334 94.64,32.944 94.64,37.414 95.809,38.583 95.809,42.469 96.012,42.672 JP8.10@97.028,42.672
  Bottom Layer w0.2: v1(86.436,30.201) 87.427,29.21 91.136,29.21 91.618,28.729 v1(91.618,28.27) ; R53.1@92.448,42.672 JP8.10@97.028,42.672
P1_7: JP8.11 R52.1 U1.55 | length 15.7
  Top Layer w0.2: U1.55@87.594,31.858 88.957,31.858 89.992,32.893 92.278,32.893 92.812,33.426 v1(92.812,38.278)
  Bottom Layer w0.2: v1(92.812,38.278) 93.642,38.278 R52.1@94.48,39.116 96.012,39.116 JP8.11@97.028,40.132
P2_2: JP8.13 R50.1 U1.39 | length 22.2
  Top Layer w0.2: U1.39@80.844,26.608 80.844,29.648 86.004,34.808 v1(86.004,35.103)
  Bottom Layer w0.2: v1(86.004,35.103) 90.653,35.103 91.338,35.789 93.743,35.789 R50.1@94.48,35.052 JP8.13@97.028,35.052
P2_6: JP8.14 R49.1 U1.56 | length 11.1
  Top Layer w0.2: U1.56@87.594,32.358 88.494,32.358 v1(88.775,32.639)
  Bottom Layer w0.2: v1(88.775,32.639) 90.297,32.639 90.551,32.893 92.1,32.893 92.456,33.249 94.201,33.249 94.48,33.528 R49.1@94.48,34.036 95.504,34.036 JP8.14@97.028,32.512
P2_7: JP8.15 R48.1 U1.57 | length 19.5
  Top Layer w0.2: v1(86.214,32.588) 86.484,32.858 U1.57@87.594,32.858
  Bottom Layer w0.2: v1(86.214,32.588) 87.255,31.547 89.814,31.547 90.754,32.487 92.598,32.487 92.801,32.69 95.098,32.69 96.114,31.674 96.114,29.972 ; R48.1@91.94,29.972 96.114,29.972 ; JP8.15@97.028,29.972 96.114,29.972
P3_3: JP8.16 R47.1 U1.42 | length 20.9
  Top Layer w0.2: U1.42@82.344,26.608 82.344,24.946 83.541,23.749 83.541,23.165 83.871,22.835 85.954,22.835 87.706,24.587 v1(87.706,26.264)
  Bottom Layer w0.2: v1(87.706,26.264) 87.706,26.137 87.986,25.857 91.694,25.857 91.796,25.756 93.82,25.756 R47.1@94.48,26.416 96.012,26.416 JP8.16@97.028,27.432
P3_4: JP8.17 R46.1 U1.44 | length 23.8
  Top Layer w0.2: U1.44@83.344,26.608 83.344,24.714 84.226,23.832 v1(84.226,23.495) ; v1(88.29,21.336) 89.154,20.472 93.497,20.472 97.028,24.003 JP8.17@97.028,24.892
  Bottom Layer w0.2: v1(84.226,23.495) 84.684,23.038 88.46,23.038 88.646,22.852 88.29,22.496 v1(88.29,21.336) ; R46.1@94.48,24.892 JP8.17@97.028,24.892
P3_5: JP8.18 R45.1 U1.45 | length 17.2
  Top Layer w0.2: U1.45@83.844,26.608 83.844,27.508 v1(87.046,27.508)
  Bottom Layer w0.2: v1(87.046,27.508) 87.046,25.781 87.376,25.451 91.338,25.451 93.828,22.962 93.87,22.962 R45.1@94.48,22.352 JP8.18@97.028,22.352
PROG: JP7.6 R33.1 U1.58 | length 36.4
  Top Layer w0.2: v1(84.734,32.537) 84.734,32.672 85.42,33.358 U1.58@87.594,33.358
  Bottom Layer w0.2: v1(84.734,32.537) 84.353,32.156 84.353,26.467 82.144,24.257 80.061,24.257 79.451,23.647 79.451,20.549 79.121,20.218 79.121,13.97 78.689,13.538 78.689,11.887 78.969,11.608 84.531,11.608 84.828,11.905 R33.1@84.828,12.192 JP7.6@86.868,12.192
PWM2: JP8.19 R44.1 U1.30 | length 39.1
  Top Layer w0.2: U1.30@75.594,29.858 77.508,29.858 77.572,29.921 78.74,29.921 79.197,29.464 79.197,28.651 78.892,28.346 77.419,28.346 76.657,27.584 76.657,21.819 78.816,19.66 81.813,19.66 82.017,19.863 92.913,19.863 93.802,18.974 97.028,18.974 JP8.19@97.028,19.812
  Bottom Layer w0.2: R44.1@94.48,21.336 95.504,21.336 JP8.19@97.028,19.812
PWM3: JP8.20 R43.1 U1.29 | length 41.6
  Top Layer w0.2: U1.29@75.594,30.358 73.386,30.358 72.39,29.362 72.39,26.314 73.584,25.121 73.584,22.25 77.394,18.44 83.896,18.44 v1(86.335,16.002) ; v1(93.929,17.602) 94.259,17.272 JP8.20@97.028,17.272
  Bottom Layer w0.2: v1(86.335,16.002) 87.083,16.002 87.935,16.854 87.935,17.678 88.595,18.339 90.754,18.339 91.135,18.72 91.135,19.101 91.415,19.38 92.247,19.38 92.71,18.917 92.71,17.602 ; R43.1@92.448,17.272 92.71,17.272 92.71,17.602 ; v1(93.929,17.602) 92.71,17.602
RESET: JP7.7 R36.1 U1.59 | length 36.7
  Top Layer w0.2: U1.59@87.594,33.858 88.443,33.858 v1(88.748,33.553)
  Bottom Layer w0.2: v1(88.748,33.553) 85.75,33.553 85.547,33.35 85.547,31.623 84.887,30.963 84.887,27.178 87.224,24.841 91.11,24.841 91.592,24.359 91.592,20.93 92.075,20.447 94.691,20.447 95.199,19.939 95.199,17.907 93.878,16.586 93.04,16.586 92.507,16.053 92.507,15.316 92.253,15.062 91.948,15.062 R36.1@91.948,14.74 91.948,14.427 91.745,14.224 89.916,14.224 JP7.7@89.408,14.732
RF_IO1: JP6.1 JP8.21 R42.1 U1.46 U7.17 | length 128
  Top Layer w0.2: U7.17@43.47,61.058 43.47,61.443 45.019,62.992 48.082,62.992 48.412,63.322 48.768,63.322 JP6.1@48.768,64.008 ; v1(47.701,66.624) 48.235,66.624 50.546,68.936 57.455,68.936 57.912,68.478 57.912,66.675 57.582,66.345 57.582,65.405 58.115,64.872 62.128,64.872 63.271,66.015 63.271,67.894 v1(63.551,68.174) ; v1(75.717,22.352) 75.717,21.971 78.435,19.253 89.611,19.253 89.992,19.253 ; v1(84.125,25.222) 84.344,25.441 U1.46@84.344,26.608 ; v1(89.611,19.202) 94.082,14.732 94.513,14.732 JP8.21@97.028,14.732
  Bottom Layer w0.2: v1(47.701,66.624) 48.768,65.557 JP6.1@48.768,64.008 ; v1(63.551,68.174) 69.494,68.174 70.815,66.853 70.815,30.709 75.717,25.806 v1(75.717,22.352) ; v1(84.125,25.222) 85.242,25.222 86.233,24.232 89.205,24.232 89.459,23.978 89.459,19.355 v1(89.611,19.202) ; R42.1@94.48,13.716 95.496,14.732 JP8.21@97.028,14.732
RF_IO2: JP6.2 JP8.22 R41.1 U1.31 U7.18 | length 114.7
  Top Layer w0.2: U7.18@42.97,61.058 42.97,60.35 43.173,60.147 44.221,60.147 46.406,62.332 v1(46.609,62.332) ; v1(45.542,67.031) 45.949,67.437 48.006,67.437 v1(48.971,68.402) ; v1(64.237,56.667) v1(72.187,56.667) ; U1.31@75.594,29.358 v1(73.66,29.358) 75.743,27.275 75.743,23.698 74.676,22.631 74.676,21.895 77.724,18.847 84.734,18.847 85.192,18.39 89.775,18.39 95.973,12.192 JP8.22@97.028,12.192
  Bottom Layer w0.2: v1(45.542,67.031) 47.498,65.075 JP6.2@47.498,64.008 47.498,63.221 v1(46.609,62.332) ; v1(48.971,68.402) 49.098,68.402 49.378,68.123 55.855,68.123 56.439,67.539 59.004,67.539 64.237,62.306 v1(64.237,56.667) ; v1(72.187,56.667) 72.187,39.649 71.476,38.938 71.476,31.542 v1(73.66,29.358) ; R41.1@94.48,12.192 JP8.22@97.028,12.192
RF_RX: JP5.3 JP8.24 R39.1 U1.48 U7.35 | length 170
  Top Layer w0.2: U7.35@33.72,57.808 32.438,57.808 29.54,60.706 29.54,62.916 JP5.3@27.432,65.024 33.452,71.044 63.602,71.044 v1(70.053,64.592) ; v1(76.987,17.17) 77.292,17.475 v1(79.985,17.475) ; v1(80.239,20.345) 86.081,20.345 v1(87.147,21.412) ; U1.48@85.344,26.608 85.344,25.527 85.776,25.095 v1(85.776,23.698)
  Bottom Layer w0.2: v1(70.053,64.592) 70.053,30.683 73.711,27.026 73.711,15.646 74.117,15.24 76.987,15.24 ; v1(76.987,17.17) 76.987,15.24 ; v1(79.985,17.475) 79.985,20.091 v1(80.239,20.345) ; v1(85.776,23.698) 88.443,23.698 89.052,23.089 89.052,21.031 88.697,20.676 87.884,20.676 v1(87.147,21.412) ; JP8.24@97.028,7.112 96.368,7.772 94.344,7.772 R39.1@93.48,8.636 93.048,8.204 91.999,8.204 91.872,8.077 90.449,8.077 90.348,8.179 86.03,8.179 83.109,5.258 79.248,5.258 76.327,8.179 76.327,12.624 76.987,13.284 76.987,15.24
RF_TX: JP5.2 JP8.23 R40.1 U1.47 U7.34 | length 198.6
  Top Layer w0.2: v1(24.663,48.336) 24.663,34.138 47.168,11.633 47.168,8.331 47.65,7.849 47.955,7.849 48.539,7.264 48.539,5.131 49.657,4.013 67.615,4.013 67.818,4.216 67.818,9.373 68.301,9.855 70.79,9.855 71.374,9.855 71.679,9.55 ; U7.34@33.72,58.308 34.407,58.308 34.62,58.522 v1(34.62,59.487) ; v1(37.033,56.845) 37.389,56.845 37.846,56.388 v1(37.846,55.169) ; v1(70.79,9.55) 71.679,9.55 ; v1(73.05,26.645) 73.939,26.645 v1(74.498,26.086) ; v1(77.597,22.403) 79.248,22.403 80.289,21.361 82.575,21.361 v1(82.702,21.488) ; v1(84.844,24.155) U1.47@84.844,26.608 ; JP8.23@97.028,9.652 95.961,8.585 84.811,8.585 84.455,8.941 72.466,8.941 ; 71.679,9.55 72.288,8.941 72.466,8.941 ; 71.679,9.55 71.857,9.55 72.466,8.941
  Bottom Layer w0.2: JP5.2@27.432,66.294 23.444,62.306 23.444,53.797 22.403,52.756 22.403,50.597 v1(24.663,48.336) 25.527,47.473 27.635,47.473 31.369,51.206 33.884,51.206 v1(37.846,55.169) ; v1(34.62,59.487) 34.62,59.258 v1(37.033,56.845) ; v1(70.79,9.55) 70.79,24.384 v1(73.05,26.645) ; v1(74.498,26.086) 74.498,22.403 75.209,21.692 76.886,21.692 v1(77.597,22.403) ; v1(82.702,21.488) 82.702,22.962 83.896,24.155 v1(84.844,24.155) ; R40.1@94.48,10.16 95.115,10.795 95.885,10.795 JP8.23@97.028,9.652
RXD1: JP7.8 R34.1 U1.27 U2.12 | length 37.9
  Top Layer w0.2: v1(73.05,21.26) 73.05,24.054 71.984,25.121 71.984,30.099 73.243,31.358 U1.27@75.594,31.358 ; v1(76.124,14.554) 76.784,13.894 ; U2.12@76.525,12.427 76.525,13.635 76.784,13.894 ; JP7.8@86.868,14.732 77.622,14.732 76.784,13.894
  Bottom Layer w0.2: v1(73.05,21.26) 73.05,15.062 73.558,14.554 v1(76.124,14.554) ; R34.1@84.828,14.732 JP7.8@86.868,14.732
SCK: JP7.3 R38.1 U1.33 | length 32
  Top Layer w0.2: U1.33@77.844,26.608 77.844,25.001 v1(77.851,24.994)
  Bottom Layer w0.2: v1(77.851,24.994) 77.851,24.003 78.647,23.207 78.647,21.522 78.257,21.133 78.257,15.126 77.876,14.745 77.876,9.754 78.435,9.195 84.277,9.195 84.887,8.585 88.341,8.585 JP7.3@89.408,9.652 90.399,9.652 90.407,9.644 R38.1@91.44,9.644
SPI_CLK: JP6.15 U4.2 U5.18 U5A.12 U6.3 U7.31 | length 127.3
  Top Layer w0.2: U7.31@36.47,61.058 36.47,59.974 v1(36.33,59.834) 36.478,59.834 v1(38.197,58.115) ; v1(39.294,33.045) 39.294,31.284 47.447,23.13 v1(47.447,17.678) ; U5A.12@46.228,21.798 47.944,21.798 48.362,22.216 U5.18@49.784,22.216 ; v1(61.201,18.402) 62.586,17.018 U6.3@64.516,17.018 v1(66.269,17.018)
  Bottom Layer w0.2: JP6.15@30.988,64.008 31.394,64.008 31.394,63.513 31.699,63.208 32.956,63.208 v1(36.33,59.834) ; v1(38.197,58.115) 43.891,58.115 44.094,57.912 44.094,55.829 43.891,55.626 43.129,55.626 41.554,54.051 41.554,52.222 42.977,50.8 43.828,50.8 47.079,47.549 49.974,47.549 50.343,47.18 50.343,46.292 49.974,45.923 47.447,45.923 44.094,42.57 42.596,42.57 41.681,41.656 41.681,39.624 43.231,38.075 43.231,36.779 42.774,36.322 41.631,36.322 40.869,35.56 40.869,34.62 v1(39.294,33.045) ; v1(47.447,17.678) 51.105,14.021 56.82,14.021 v1(61.201,18.402) ; U4.2@64.516,37.973 66.7,37.973 67.259,37.414 67.259,34.442 66.599,33.782 66.599,17.348 v1(66.269,17.018)
SPI_MISO: JP6.14 U5.20 U5A.14 U6.2 U7.30 | length 113.6
  Top Layer w0.2: JP6.14@32.258,64.008 33.477,62.789 36.582,62.789 36.97,62.401 U7.30@36.97,61.058 ; v1(33.477,69.088) 45.974,69.088 v1(46.076,69.19) ; v1(45.212,23.876) 46.19,22.898 U5A.14@46.228,22.898 ; v1(48.311,23.216) 51.46,23.216 52.432,22.244 52.432,20.212 52.832,19.812 v1(52.832,15.24) ; v1(53.137,27.356) 53.137,30.505 54.61,31.979 54.61,40.03 54.381,40.259 v1(54.051,40.259) ; v1(62.433,16.383) U6.2@64.516,16.383
  Bottom Layer w0.2: JP6.14@32.258,64.008 32.258,65.583 33.477,66.802 v1(33.477,69.088) ; v1(45.212,23.876) 47.651,23.876 v1(48.311,23.216) 52.451,27.356 v1(53.137,27.356) ; v1(46.076,69.19) 46.533,68.732 47.422,68.732 48.463,67.691 52.984,67.691 54.458,66.218 54.458,60.173 54,59.715 54,58.09 54.051,58.039 v1(54.051,40.259) ; v1(52.832,15.24) 54.254,15.062 58.318,19.126 62.027,19.126 62.433,18.72 v1(62.433,16.383)
SPI_MOSI: JP6.13 U4.1 U5.19 U5A.13 U6.1 U7.29 | length 144.9
  Top Layer w0.2: JP6.13@33.528,64.008 33.528,63.525 33.68,63.525 34.011,63.195 37.064,63.195 37.47,62.789 U7.29@37.47,61.058 ; v1(44.9,22.352) 44.904,22.348 U5A.13@46.228,22.348 ; U5.19@49.784,22.716 51.206,22.716 51.816,21.844 51.898,19.815 52.197,12.395 53.086,11.506 58.166,11.506 59.461,12.802 61.366,12.802 62.586,14.021 62.586,14.834 63.5,15.748 U6.1@64.516,15.748 65.329,15.748 66.294,14.783 69.743,14.783 v1(70.028,15.068) ; v1@51.308,19.812 51.816,19.812
  Bottom Layer w0.2: JP6.13@33.528,64.008 37.541,68.021 43.967,68.021 46.99,71.044 57.709,71.044 58.039,70.714 58.039,69.748 64.897,62.89 64.897,43.205 64.186,42.494 64.186,40.513 62.586,40.513 62.128,40.056 62.128,39.065 62.586,38.608 U4.1@64.516,38.608 66.65,38.608 67.666,37.592 67.666,33.909 67.234,33.477 67.234,30.456 68.581,29.108 69.571,29.108 70.028,28.651 v1(70.028,15.068) ; v1(44.9,22.352) 49.784,22.352 49.784,19.812 v1@51.308,19.812
  other v1: 51.2,19.812
TXD1: JP7.10 R35.1 U1.28 U2.11 | length 38.4
  Top Layer w0.2: U1.28@75.594,30.858 v1(76.784,30.858) ; v1(77.175,11.049) U2.11@77.175,12.427 77.175,13.319 77.419,13.564 79.731,13.564 79.985,13.31 v1(81.763,13.31)
  Bottom Layer w0.2: v1(76.784,30.858) 76.784,24.333 78.247,22.87 78.247,21.742 77.775,21.27 77.775,15.678 77.394,15.297 77.394,11.268 v1(77.175,11.049) ; v1(81.763,13.31) 83.261,14.808 83.261,17.831 84.379,17.831 84.379,17.272 R35.1@84.828,17.272 JP7.10@86.868,17.272
pads on no net: J2.3 J3.1 J3.4 J3.6 J3.7 J3.8 J3.9 J3.10 J3.11 JP1.4 JP1.6 JP1.8 JP1.10 JP1.12 JP1.13 JP1.14 P1.2@85.842,65.522 P1.2@85.842,70.622 P1.2@90.942,65.522 R63.2 S1.1@59.726,65.951 S1.2@64.226,58.001 S2.1@59.726,52.235 S2.2@64.226,44.285 S3.1@59.726,38.011 S3.2@64.226,30.061 U1.13 U2.7 U2.8 U2.9 U2.10 U5.1 U5.2 U5.3 U5.4 U5.7 U5.8 U5.9 U5.10 U5.13 U5.14 U5.15 U5.16 U5.21 U5.22 U5.23 U5.24 U5.25 U5.26 U5.27 U5.28 U5.29 U5.30 U5.31 U5.32 U5.33 U5.34 U5.35 U5.36 U5.37 U5.38 U5.39 U5.40 U5.41 U5.42 U5.43 U5.44 U5.45 U5.46 U5.47 U5.48 U5A.3 U5A.4 U5A.5 U5A.8 U5A.9 U5A.10 U5A.15 U5A.16 U5A.17 U5A.18 U5A.19 U5A.20 U5A.21 U5A.22 U5A.23 U5A.24 U5A.25 U5A.26 U5A.27 U5A.28 U6.5 U6.11 U6.12 U6.13 Y4.1@69.725,37.945 Y4.2@67.435,24.031
copper on no net: | length 66.8
  Top Layer w0.2: 90.52,62.476 90.528,62.484
  Top Layer w0.4: 73.152,72.644 73.152,72.136 73.152,62.992 77.724,62.992 77.724,71.12 74.168,71.12 74.168,64.516 ; 73.152,72.7 94.488,72.7 ; 89.916,62.476 90.52,62.476 ; 90.528,62.484 91.44,62.484 94.488,65.532 94.488,72.644

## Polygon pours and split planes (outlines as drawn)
GND on GND Plane (split plane): 0.508,0.508 0.508,73.492 98.492,73.492 98.492,0.508
3.3V on 3V Plane (split plane): 0.508,0.508 0.508,73.492 98.492,73.492 98.492,0.508

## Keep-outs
Keep-Out Layer:
  lines w0.2: 0.8,0.8 98.2,0.8 98.2,73.2 0.8,73.2 0.8,0.8

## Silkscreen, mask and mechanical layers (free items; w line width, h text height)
Drill Drawing:
  text ".LEGEND" at 104.08,5.08 h1.52
  text "Drill Drawing." at 104.08,2.54 h1.52

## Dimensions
0.8,0.8 to 98.2,0.8 on Mechanical 1
0.8,0.8 to 0.8,73.2 on Mechanical 1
